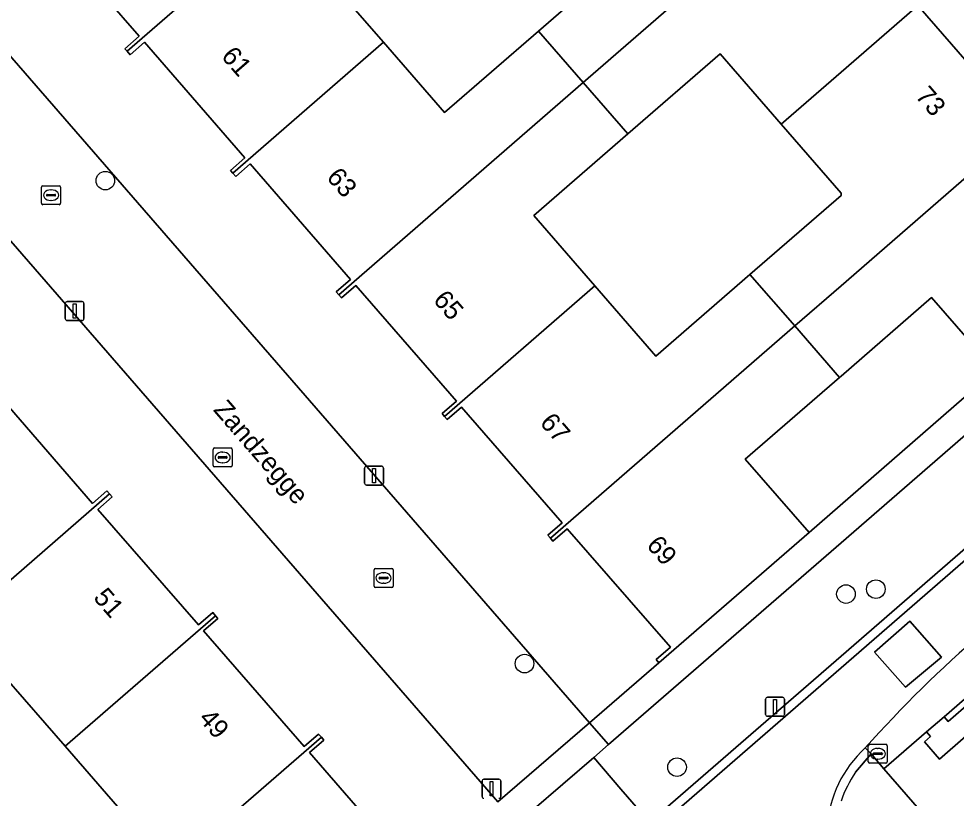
# Model space of a CAD drawing. Extents: x 155887 to 156869, y 383880 to 384678.
# Drawn here: x 156456.68 to 156506.07, y 384198.56 to 384239.64 of the extents above; entities that cross this region are included whole.
import ezdxf

# ---------------------------------------------------------------- set-up
doc = ezdxf.new("R2010")
doc.units = 0
for name, color, linetype in [('IMGEO_Boom', 7, 'Continuous'), ('IMGEO_Brandkraan', 7, 'Continuous'), ('IMGEO_Erf', 7, 'Continuous'), ('IMGEO_Kolk', 7, 'Continuous'), ('IMGEO_Lichtmast', 7, 'Continuous'), ('IMGEO_Muur', 7, 'Continuous'), ('IMGEO_Openbare_ruimte_label', 7, 'Continuous'), ('IMGEO_Pand', 7, 'Continuous'), ('IMGEO_Pand_nummerreeks', 7, 'Continuous'), ('IMGEO_Parkeervlak_open', 7, 'Continuous'), ('IMGEO_Rijbaan_lokaal_gesloten', 7, 'Continuous'), ('IMGEO_Rijbaan_lokaal_open', 7, 'Continuous'), ('IMGEO_Voetpad_open', 7, 'Continuous')]:
    doc.layers.add(name, color=color, linetype=linetype)

msp = doc.modelspace()

# ---------------------------------------------------------------- linework, layer by layer
at = {"layer": 'IMGEO_Boom'}
for centre in [(156461.247, 384231.107), (156501.836, 384209.58), (156500.259, 384209.32), (156483.328, 384205.656), (156491.362, 384200.197)]:
    msp.add_circle(centre, 0.489, dxfattribs=at)
at = {"layer": 'IMGEO_Brandkraan'}
for p, q in [((156466.924, 384216.093), (156466.924, 384216.945)), ((156466.999, 384217.019), (156467.851, 384217.019)), ((156467.925, 384216.945), (156467.925, 384216.093)), ((156467.183, 384216.513), (156467.183, 384216.525)), ((156467.621, 384216.476), (156467.223, 384216.476)), ((156467.226, 384216.562), (156467.624, 384216.562)), ((156467.412, 384216.799), (156467.437, 384216.799)), ((156467.667, 384216.525), (156467.667, 384216.513)), ((156467.851, 384216.019), (156466.999, 384216.019)), ((156467.435, 384216.239), (156467.41, 384216.239)), ((156501.434, 384200.479), (156501.434, 384201.331)), ((156501.509, 384201.405), (156502.361, 384201.405)), ((156501.922, 384201.185), (156501.947, 384201.185)), ((156502.435, 384201.331), (156502.435, 384200.479)), ((156501.693, 384200.899), (156501.693, 384200.911)), ((156502.131, 384200.862), (156501.733, 384200.862)), ((156501.736, 384200.948), (156502.134, 384200.948)), ((156501.945, 384200.625), (156501.92, 384200.625)), ((156502.177, 384200.911), (156502.177, 384200.899)), ((156502.361, 384200.405), (156501.509, 384200.405))]:
    msp.add_line(p, q, dxfattribs=at)
for points in [[(156466.924, 384216.093), (156466.924, 384216.945)], [(156466.999, 384217.019), (156467.851, 384217.019)], [(156467.925, 384216.945), (156467.925, 384216.093)], [(156467.851, 384216.019), (156466.999, 384216.019)], [(156501.434, 384200.479), (156501.434, 384201.331)], [(156501.509, 384201.405), (156502.361, 384201.405)], [(156502.435, 384201.331), (156502.435, 384200.479)], [(156502.361, 384200.405), (156501.509, 384200.405)]]:
    msp.add_lwpolyline(points, dxfattribs=at)
for centre, radius, start, end in [((156467.001, 384216.943), 0.0765, 91.552, 178.448), ((156467.001, 384216.943), 0.0765, 91.552, 178.448), ((156467.849, 384216.943), 0.0765, 1.552, 88.448), ((156467.849, 384216.943), 0.0765, 1.552, 88.448), ((156467.223, 384216.522), 0.0403, 85.8775, 175.7526), ((156467.22, 384216.512), 0.0366, 178.938, 274.7102), ((156467.624, 384216.519), 0.043, 264.8664, 352.4533), ((156467.628, 384216.524), 0.0386, 1.7309, 96.639), ((156467.001, 384216.095), 0.0765, 181.552, 268.448), ((156467.001, 384216.095), 0.0765, 181.552, 268.448), ((156467.849, 384216.095), 0.0765, 271.552, 358.448), ((156467.849, 384216.095), 0.0765, 271.552, 358.448), ((156501.511, 384201.329), 0.0765, 91.552, 178.448), ((156501.511, 384201.329), 0.0765, 91.552, 178.448), ((156502.359, 384201.329), 0.0765, 1.552, 88.448), ((156502.359, 384201.329), 0.0765, 1.552, 88.448), ((156501.733, 384200.908), 0.0403, 85.8775, 175.7526), ((156501.73, 384200.898), 0.0366, 178.938, 274.7102), ((156502.134, 384200.905), 0.043, 264.8664, 352.4533), ((156502.138, 384200.91), 0.0386, 1.7309, 96.639), ((156501.511, 384200.481), 0.0765, 181.552, 268.448), ((156501.511, 384200.481), 0.0765, 181.552, 268.448), ((156502.359, 384200.481), 0.0765, 271.552, 358.448), ((156502.359, 384200.481), 0.0765, 271.552, 358.448)]:
    msp.add_arc(centre, radius, start, end, dxfattribs=at)
for centre, major_axis, ratio, start_param, end_param in [((156467.411, 384216.519), (-0.387, 0.002), 0.722429, 4.712389, 7.853982), ((156467.436, 384216.519), (-0.39, 0.002), 0.717154, 1.570796, 4.712389), ((156501.921, 384200.905), (-0.387, 0.002), 0.722429, 4.712389, 7.853982), ((156501.946, 384200.905), (-0.39, 0.002), 0.717154, 1.570796, 4.712389)]:
    msp.add_ellipse(centre, major_axis=major_axis, ratio=ratio, start_param=start_param, end_param=end_param, dxfattribs=at)
at = {"layer": 'IMGEO_Erf'}
for points in [[(156479.114, 384234.691), (156484.066, 384238.989), (156488.927, 384243.208), (156485.703, 384246.922), (156483.032, 384250), (156482.503, 384250.609), (156481.801, 384250), (156477.64, 384246.388), (156472.69, 384242.092), (156475.895, 384238.399)], [(156500, 384230.329), (156500, 384230.446), (156496.844, 384234.082), (156493.635, 384237.78), (156488.777, 384233.564), (156483.821, 384229.263), (156487.037, 384225.558), (156490.244, 384221.862), (156495.203, 384226.165)], [(156508.113, 384221.097), (156504.771, 384224.949), (156500, 384220.809), (156499.918, 384220.737), (156494.957, 384216.432), (156498.314, 384212.563)], [(156504.508, 384202.058), (156504.718, 384201.816), (156504.393, 384201.534), (156505.18, 384200.628), (156509.637, 384204.498), (156508.866, 384205.417), (156505.635, 384202.609), (156505.425, 384202.851)], [(156459.122, 384201.298), (156455.915, 384204.988), (156450.865, 384200.599), (156451.631, 384199.716), (156456.534, 384194.093), (156457.297, 384193.205), (156462.343, 384197.591)]]:
    msp.add_lwpolyline(points, close=True, dxfattribs=at)
for points in [[(156453.061, 384241.329), (156486.746, 384202.533), (156490.404, 384205.705), (156490.264, 384205.866), (156491.013, 384206.514), (156485.582, 384212.763), (156484.827, 384212.107), (156484.691, 384212.264), (156484.551, 384212.425), (156485.306, 384213.081), (156480.013, 384219.171), (156479.258, 384218.515), (156479.118, 384218.676), (156478.982, 384218.833), (156479.736, 384219.489), (156474.443, 384225.579), (156473.689, 384224.923), (156473.546, 384225.088), (156473.413, 384225.241), (156474.168, 384225.897), (156468.875, 384231.987), (156468.12, 384231.331), (156467.965, 384231.508), (156467.843, 384231.648), (156468.599, 384232.305), (156463.306, 384238.394), (156462.551, 384237.738), (156462.393, 384237.92), (156462.274, 384238.056), (156463.029, 384238.712), (156457.598, 384244.961)], [(156504.174, 384240.191), (156509.463, 384234.099)], [(156481.913, 384198.365), (156448.242, 384237.145)], [(156455.279, 384220.188), (156460.575, 384214.099), (156461.33, 384214.755), (156461.465, 384214.6), (156461.605, 384214.439), (156460.851, 384213.783), (156466.146, 384207.695), (156466.901, 384208.351), (156467.048, 384208.181), (156467.176, 384208.034), (156466.422, 384207.378), (156471.717, 384201.289), (156472.472, 384201.945), (156472.624, 384201.771), (156472.748, 384201.629), (156471.993, 384200.972), (156477.427, 384194.725)]]:
    msp.add_lwpolyline(points, dxfattribs=at)
at = {"layer": 'IMGEO_Kolk'}
for p, q in [((156457.886, 384229.914), (156457.886, 384230.766)), ((156457.961, 384230.84), (156458.813, 384230.84)), ((156458.887, 384230.766), (156458.887, 384229.914)), ((156458.145, 384230.334), (156458.145, 384230.346)), ((156458.583, 384230.297), (156458.185, 384230.297)), ((156458.188, 384230.383), (156458.586, 384230.383)), ((156458.374, 384230.62), (156458.399, 384230.62)), ((156458.629, 384230.346), (156458.629, 384230.334)), ((156458.813, 384229.84), (156457.961, 384229.84)), ((156458.397, 384230.06), (156458.372, 384230.06)), ((156475.403, 384209.741), (156475.403, 384210.593)), ((156475.478, 384210.667), (156476.33, 384210.667)), ((156476.404, 384210.593), (156476.404, 384209.741)), ((156475.662, 384210.161), (156475.662, 384210.173)), ((156476.1, 384210.124), (156475.702, 384210.124)), ((156475.705, 384210.21), (156476.103, 384210.21)), ((156475.891, 384210.447), (156475.916, 384210.447)), ((156476.146, 384210.173), (156476.146, 384210.161)), ((156476.33, 384209.667), (156475.478, 384209.667)), ((156475.914, 384209.887), (156475.889, 384209.887))]:
    msp.add_line(p, q, dxfattribs=at)
for points in [[(156457.886, 384229.914), (156457.886, 384230.766)], [(156457.961, 384230.84), (156458.813, 384230.84)], [(156458.887, 384230.766), (156458.887, 384229.914)], [(156458.813, 384229.84), (156457.961, 384229.84)], [(156475.403, 384209.741), (156475.403, 384210.593)], [(156475.478, 384210.667), (156476.33, 384210.667)], [(156476.404, 384210.593), (156476.404, 384209.741)], [(156476.33, 384209.667), (156475.478, 384209.667)]]:
    msp.add_lwpolyline(points, dxfattribs=at)
for centre, radius, start, end in [((156457.963, 384230.764), 0.0765, 91.552, 178.448), ((156457.963, 384230.764), 0.0765, 91.552, 178.448), ((156458.811, 384230.764), 0.0765, 1.552, 88.448), ((156458.811, 384230.764), 0.0765, 1.552, 88.448), ((156458.185, 384230.343), 0.0403, 85.8775, 175.7526), ((156458.182, 384230.333), 0.0366, 178.938, 274.7102), ((156458.586, 384230.34), 0.043, 264.8664, 352.4533), ((156458.59, 384230.345), 0.0386, 1.7309, 96.639), ((156457.963, 384229.916), 0.0765, 181.552, 268.448), ((156457.963, 384229.916), 0.0765, 181.552, 268.448), ((156458.811, 384229.916), 0.0765, 271.552, 358.448), ((156458.811, 384229.916), 0.0765, 271.552, 358.448), ((156475.48, 384210.591), 0.0765, 91.552, 178.448), ((156475.48, 384210.591), 0.0765, 91.552, 178.448), ((156476.328, 384210.591), 0.0765, 1.552, 88.448), ((156476.328, 384210.591), 0.0765, 1.552, 88.448), ((156475.702, 384210.17), 0.0403, 85.8775, 175.7526), ((156475.699, 384210.16), 0.0366, 178.938, 274.7102), ((156476.103, 384210.167), 0.043, 264.8664, 352.4533), ((156476.107, 384210.172), 0.0386, 1.7309, 96.639), ((156475.48, 384209.743), 0.0765, 181.552, 268.448), ((156475.48, 384209.743), 0.0765, 181.552, 268.448), ((156476.328, 384209.743), 0.0765, 271.552, 358.448), ((156476.328, 384209.743), 0.0765, 271.552, 358.448)]:
    msp.add_arc(centre, radius, start, end, dxfattribs=at)
for centre, major_axis, ratio, start_param, end_param in [((156458.373, 384230.34), (-0.387, 0.002), 0.722429, 4.712389, 7.853982), ((156458.398, 384230.34), (-0.39, 0.002), 0.717154, 1.570796, 4.712389), ((156475.89, 384210.167), (-0.387, 0.002), 0.722429, 4.712389, 7.853982), ((156475.915, 384210.167), (-0.39, 0.002), 0.717154, 1.570796, 4.712389)]:
    msp.add_ellipse(centre, major_axis=major_axis, ratio=ratio, start_param=start_param, end_param=end_param, dxfattribs=at)
at = {"layer": 'IMGEO_Lichtmast'}
for p, q in [((156459.131, 384223.834), (156459.131, 384224.634)), ((156459.131, 384224.634), (156459.131, 384223.834)), ((156459.231, 384224.734), (156460.021, 384224.734)), ((156460.021, 384224.734), (156459.231, 384224.734)), ((156460.121, 384224.634), (156460.121, 384223.834)), ((156460.121, 384223.834), (156460.121, 384224.634)), ((156460.021, 384223.734), (156459.231, 384223.734)), ((156459.231, 384223.734), (156460.021, 384223.734)), ((156474.902, 384215.16), (156474.902, 384215.96)), ((156474.902, 384215.96), (156474.902, 384215.16)), ((156475.002, 384216.06), (156475.792, 384216.06)), ((156475.792, 384216.06), (156475.002, 384216.06)), ((156475.892, 384215.96), (156475.892, 384215.16)), ((156475.892, 384215.16), (156475.892, 384215.96)), ((156475.792, 384215.06), (156475.002, 384215.06)), ((156475.002, 384215.06), (156475.792, 384215.06)), ((156496.026, 384202.982), (156496.026, 384203.782)), ((156496.026, 384203.782), (156496.026, 384202.982)), ((156496.126, 384203.882), (156496.916, 384203.882)), ((156496.916, 384203.882), (156496.126, 384203.882)), ((156497.016, 384203.782), (156497.016, 384202.982)), ((156497.016, 384202.982), (156497.016, 384203.782)), ((156496.916, 384202.882), (156496.126, 384202.882)), ((156496.126, 384202.882), (156496.916, 384202.882)), ((156481.09, 384198.66), (156481.09, 384199.46)), ((156481.09, 384199.46), (156481.09, 384198.66)), ((156481.19, 384199.56), (156481.98, 384199.56)), ((156481.98, 384199.56), (156481.19, 384199.56)), ((156482.08, 384199.46), (156482.08, 384198.66)), ((156482.08, 384198.66), (156482.08, 384199.46))]:
    msp.add_line(p, q, dxfattribs=at)
for points in [[(156459.551, 384224.609), (156459.701, 384224.609), (156459.701, 384223.859), (156459.551, 384223.859), (156459.551, 384224.609)], [(156475.322, 384215.935), (156475.472, 384215.935), (156475.472, 384215.185), (156475.322, 384215.185), (156475.322, 384215.935)], [(156496.446, 384203.757), (156496.596, 384203.757), (156496.596, 384203.007), (156496.446, 384203.007), (156496.446, 384203.757)], [(156481.51, 384199.435), (156481.66, 384199.435), (156481.66, 384198.685), (156481.51, 384198.685), (156481.51, 384199.435)]]:
    msp.add_lwpolyline(points, dxfattribs=at)
for centre, start, end in [((156459.231, 384224.634), 90, 180), ((156459.231, 384224.634), 90, 180), ((156460.021, 384224.634), 0, 90), ((156460.021, 384224.634), 360, 90), ((156459.231, 384223.834), 180, 270), ((156459.231, 384223.834), 180, 270), ((156460.021, 384223.834), 270, 0), ((156460.021, 384223.834), 270, 0), ((156475.002, 384215.96), 90, 180), ((156475.002, 384215.96), 90, 180), ((156475.792, 384215.96), 0, 90), ((156475.792, 384215.96), 360, 90), ((156475.002, 384215.16), 180, 270), ((156475.002, 384215.16), 180, 270), ((156475.792, 384215.16), 270, 0), ((156475.792, 384215.16), 270, 0), ((156496.126, 384203.782), 90, 180), ((156496.126, 384203.782), 90, 180), ((156496.916, 384203.782), 0, 90), ((156496.916, 384203.782), 360, 90), ((156496.126, 384202.982), 180, 270), ((156496.126, 384202.982), 180, 270), ((156496.916, 384202.982), 270, 0), ((156496.916, 384202.982), 270, 0), ((156481.19, 384199.46), 90, 180), ((156481.19, 384199.46), 90, 180), ((156481.98, 384199.46), 0, 90), ((156481.98, 384199.46), 360, 90), ((156481.19, 384198.66), 180, 270), ((156481.19, 384198.66), 180, 270), ((156481.98, 384198.66), 270, 0), ((156481.98, 384198.66), 270, 0)]:
    msp.add_arc(centre, 0.1, start, end, dxfattribs=at)
at = {"layer": 'IMGEO_Muur'}
msp.add_lwpolyline([(156498.314, 384212.563), (156508.113, 384221.097)], dxfattribs=at)
msp.add_lwpolyline([(156505.425, 384202.851), (156505.635, 384202.609), (156508.866, 384205.417), (156509.637, 384204.498), (156509.89, 384204.718), (156509.103, 384205.623), (156512.333, 384208.43), (156512.123, 384208.672)], close=True, dxfattribs=at)
at = {"layer": 'IMGEO_Pand'}
for points in [[(156486.421, 384236.278), (156499.231, 384247.41), (156499.087, 384247.576), (156498.332, 384246.92), (156495.659, 384250), (156493.043, 384253.013), (156493.798, 384253.668), (156493.656, 384253.832), (156489.246, 384250), (156485.703, 384246.922), (156488.927, 384243.208), (156484.066, 384238.989)], [(156463.052, 384250), (156456.692, 384244.48), (156456.841, 384244.308), (156457.598, 384244.961), (156463.029, 384238.712), (156462.274, 384238.056), (156462.393, 384237.92), (156475.277, 384249.109), (156474.503, 384250), (156472.925, 384251.817), (156470.832, 384250), (156467.977, 384247.522), (156465.826, 384250), (156464.634, 384251.373)], [(156475.895, 384238.399), (156472.69, 384242.092), (156477.64, 384246.388), (156475.277, 384249.109), (156462.393, 384237.92), (156462.551, 384237.738), (156463.306, 384238.394), (156468.599, 384232.305), (156467.843, 384231.648), (156467.965, 384231.508)], [(156486.421, 384236.278), (156488.777, 384233.564), (156493.635, 384237.78), (156496.844, 384234.082), (156500, 384236.825), (156504.799, 384240.996), (156504.653, 384241.164), (156503.898, 384240.509), (156500, 384244.999), (156498.608, 384246.602), (156499.363, 384247.258), (156499.231, 384247.41)], [(156504.799, 384240.996), (156500, 384236.825), (156496.844, 384234.082), (156500, 384230.446), (156500, 384230.329), (156495.203, 384226.165), (156497.561, 384223.45), (156500, 384225.57), (156510.368, 384234.581), (156510.218, 384234.754), (156509.463, 384234.099), (156504.174, 384240.191), (156504.929, 384240.846)], [(156486.421, 384236.278), (156484.066, 384238.989), (156479.114, 384234.691), (156475.895, 384238.399), (156467.965, 384231.508), (156468.12, 384231.331), (156468.875, 384231.987), (156474.168, 384225.897), (156473.413, 384225.241), (156473.546, 384225.088)], [(156486.421, 384236.278), (156473.546, 384225.088), (156473.689, 384224.923), (156474.443, 384225.579), (156479.736, 384219.489), (156478.982, 384218.833), (156479.118, 384218.676), (156487.037, 384225.558), (156483.821, 384229.263), (156488.777, 384233.564)], [(156499.918, 384220.737), (156500, 384220.809), (156504.771, 384224.949), (156508.113, 384221.097), (156516.06, 384228.023), (156515.919, 384228.186), (156515.166, 384227.529), (156509.739, 384233.781), (156510.494, 384234.436), (156510.368, 384234.581), (156500, 384225.57), (156497.561, 384223.45)], [(156487.037, 384225.558), (156479.118, 384218.676), (156479.258, 384218.515), (156480.013, 384219.171), (156485.306, 384213.081), (156484.551, 384212.425), (156484.691, 384212.264), (156497.561, 384223.45), (156495.203, 384226.165), (156490.244, 384221.862)], [(156499.918, 384220.737), (156497.561, 384223.45), (156484.691, 384212.264), (156484.827, 384212.107), (156485.582, 384212.763), (156491.013, 384206.514), (156490.264, 384205.866), (156490.404, 384205.705), (156498.314, 384212.563), (156494.957, 384216.432)], [(156448.498, 384203.327), (156461.465, 384214.6), (156461.33, 384214.755), (156460.575, 384214.099), (156455.279, 384220.188), (156456.033, 384220.844), (156455.896, 384221.002), (156447.974, 384214.124), (156451.186, 384210.428), (156446.141, 384206.043)], [(156448.498, 384203.327), (156450.865, 384200.599), (156455.915, 384204.988), (156459.122, 384201.298), (156467.048, 384208.181), (156466.901, 384208.351), (156466.146, 384207.695), (156460.851, 384213.783), (156461.605, 384214.439), (156461.465, 384214.6)], [(156459.646, 384190.5), (156472.624, 384201.771), (156472.472, 384201.945), (156471.717, 384201.289), (156466.422, 384207.378), (156467.176, 384208.034), (156467.048, 384208.181), (156459.122, 384201.298), (156462.343, 384197.591), (156457.297, 384193.205)], [(156509.637, 384204.498), (156505.18, 384200.628), (156504.393, 384201.534), (156504.718, 384201.816), (156504.508, 384202.058), (156502.257, 384200.103), (156512.362, 384188.479), (156512.604, 384188.689), (156512.505, 384188.802), (156515.103, 384191.058), (156511.625, 384195.063), (156515.179, 384198.149)], [(156459.646, 384190.5), (156462.011, 384187.777), (156467.059, 384192.164), (156470.389, 384188.333), (156477.559, 384194.574), (156478.3, 384195.219), (156478.169, 384195.371), (156477.427, 384194.725), (156471.993, 384200.972), (156472.748, 384201.629), (156472.624, 384201.771)]]:
    msp.add_lwpolyline(points, close=True, dxfattribs=at)
at = {"layer": 'IMGEO_Parkeervlak_open'}
msp.add_lwpolyline([(156522.949, 384225.984), (156521.456, 384227.719), (156522.926, 384229.023), (156521.497, 384230.686), (156500, 384212.021), (156487.753, 384201.388), (156486.972, 384200.71), (156488.402, 384199.038), (156489.913, 384197.295), (156490.753, 384198.024), (156500, 384206.046)], close=True, dxfattribs=at)
at = {"layer": 'IMGEO_Rijbaan_lokaal_gesloten'}
msp.add_lwpolyline([(156557.467, 384248.05), (156553.99, 384252.361), (156553.135, 384251.635), (156551.256, 384250), (156547.776, 384246.974), (156547.528, 384246.758), (156546.36, 384245.735), (156545.502, 384244.98), (156537.299, 384237.854), (156529.516, 384231.093), (156523.251, 384225.637), (156500, 384205.436), (156491.733, 384198.254), (156491.055, 384197.674), (156493.377, 384194.981), (156497.577, 384190.155), (156500.691, 384192.754)], dxfattribs=at)
msp.add_lwpolyline([(156505.293, 384205.994), (156503.395, 384204.412), (156501.76, 384206.259), (156503.631, 384207.891)], close=True, dxfattribs=at)
for centre, radius, start, end in [((156550.862, 384156.992), 66.441, 130.81095, 138.27039), ((156505.394, 384196.679), 6.126, 132.218, 219.8456)]:
    msp.add_arc(centre, radius, start, end, dxfattribs=at)
at = {"layer": 'IMGEO_Rijbaan_lokaal_open'}
for points in [[(156453.061, 384241.329), (156451.452, 384239.846), (156449.822, 384238.517), (156448.242, 384237.145), (156481.913, 384198.365), (156486.746, 384202.533)], [(156503.395, 384204.412), (156505.293, 384205.994), (156503.631, 384207.891), (156501.76, 384206.259)], [(156488.402, 384199.038), (156486.972, 384200.71), (156483.706, 384197.89), (156485.158, 384196.251), (156486.678, 384194.498), (156489.913, 384197.295)]]:
    msp.add_lwpolyline(points, close=True, dxfattribs=at)
msp.add_lwpolyline([(156522.949, 384225.984), (156500, 384206.046), (156490.753, 384198.024), (156489.913, 384197.295), (156486.678, 384194.498), (156473.803, 384183.315), (156471.243, 384181.117), (156471.543, 384180.768), (156474.104, 384182.967), (156485.441, 384192.82), (156491.055, 384197.674), (156491.733, 384198.254), (156500, 384205.436), (156523.251, 384225.637)], dxfattribs=at)
at = {"layer": 'IMGEO_Voetpad_open'}
msp.add_lwpolyline([(156521.497, 384230.686), (156524.756, 384233.539), (156533.99, 384241.564), (156543.11, 384249.489), (156542.133, 384250.656), (156536.049, 384245.383), (156532.979, 384242.697), (156528.897, 384239.125), (156528.133, 384238.467), (156524.533, 384235.366), (156519.712, 384231.205), (156516.06, 384228.023), (156508.113, 384221.097), (156498.314, 384212.563), (156490.404, 384205.705), (156486.746, 384202.533), (156487.753, 384201.388), (156500, 384212.021)], close=True, dxfattribs=at)
for points in [[(156504.508, 384202.058), (156505.425, 384202.851), (156512.123, 384208.672), (156513.039, 384209.467), (156515.05, 384211.218), (156517.346, 384213.216), (156518.263, 384214.011), (156524.939, 384219.822), (156525.856, 384220.614), (156528.027, 384222.491), (156530.174, 384224.347), (156531.089, 384225.151), (156537.787, 384230.955), (156538.702, 384231.752), (156540.977, 384233.732), (156544.066, 384236.402), (156547.567, 384239.428)], [(156483.706, 384197.89), (156486.972, 384200.71), (156487.753, 384201.388), (156486.746, 384202.533), (156481.913, 384198.365)], [(156501.278, 384201.216), (156501.585, 384200.905), (156502.257, 384200.103), (156504.508, 384202.058)], [(156500.757, 384199.93), (156501.585, 384200.905), (156501.278, 384201.216)], [(156526.237, 384172.47), (156524.662, 384174.288), (156522.599, 384176.668), (156521.814, 384177.584), (156515.999, 384184.242), (156515.188, 384185.183), (156513.124, 384187.569), (156512.362, 384188.479), (156502.257, 384200.103), (156501.585, 384200.905), (156500.757, 384199.93)]]:
    msp.add_lwpolyline(points, dxfattribs=at)
for centre, radius, start, end in [((156550.862, 384156.992), 66.441, 130.81095, 138.27039), ((156505.394, 384196.679), 6.126, 132.218, 219.8456), ((156506.684, 384196.03), 7.095, 146.6529, 160.3981), ((156506.684, 384196.03), 7.095, 146.6529, 160.3981)]:
    msp.add_arc(centre, radius, start, end, dxfattribs=at)

# ---------------------------------------------------------------- texts
at = {"layer": 'IMGEO_Openbare_ruimte_label'}
msp.add_text('Zandzegge', height=1, rotation=310.9433, dxfattribs=at).set_placement((156466.895, 384219.008))
at = {"layer": 'IMGEO_Pand_nummerreeks'}
for s, rotation, p in [('61', 310.9945, (156467.308, 384237.632)), ('73', 310.9624, (156503.87, 384235.538)), ('63', 310.9945, (156472.852, 384231.253)), ('65', 310.9945, (156478.469, 384224.79)), ('67', 310.9945, (156484.087, 384218.326)), ('69', 310.9945, (156489.705, 384211.863)), ('51', 311.0175, (156460.571, 384209.106)), ('49', 311.0175, (156466.115, 384202.733))]:
    msp.add_text(s, height=1, rotation=rotation, dxfattribs=at).set_placement(p)

doc.saveas('drawing.dxf')
